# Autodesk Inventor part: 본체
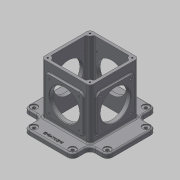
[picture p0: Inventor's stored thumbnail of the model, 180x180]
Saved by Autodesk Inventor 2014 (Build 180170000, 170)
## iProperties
Created: 2018-09
Part Number: 본체
Material: 알루미늄 6061
Document SubType Name: Modeling
Designer: mduedu
Density: 2.71 g/cm^3
Appearance: 기본값
Mass: 1126.64 g
Surface Area: 1144.86 cm^2
Volume: 415.735 cm^3
Author: mduedu
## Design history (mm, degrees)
sketch "스케치1"
  geometry: L1 (90, 52.5)-(-90, 52.5); L2 (-90, 52.5)-(-90, -52.5); L3 (-90, -52.5)-(90, -52.5); L4 (90, -52.5)-(90, 52.5); L5 (90, 52.5)-(-90, -52.5); L6 (-90, 52.5)-(90, -52.5); L7 (-52.5, -90)-(52.5, -90); L8 (52.5, -90)-(52.5, 90); L9 (52.5, 90)-(-52.5, 90); L10 (-52.5, 90)-(-52.5, -90); L11 (-52.5, -90)-(52.5, 90); L12 (52.5, -90)-(-52.5, 90); 1 further point
  constraints: 24 end point, 4 midpoint, 4 parallel, 2 horizontal, 2 perpendicular
  dimensions: "d0" = 180 distance of L3.end L2.end; "d1" = 105 distance of L2.end L1.end; "d105" = 105 distance of L9.end L8.end; "d106" = 180 distance of L8.end L7.end
extrude "돌출1" new body sketch "스케치1" distance "d2" = 10; taper "d3" = 0 deg
fillet "모깎기16" dims "d107" = 11
sketch "스케치2"
  geometry: L1 (-52.5, -52.5)-(52.5, -52.5); L2 (52.5, -52.5)-(52.5, 52.5); L3 (52.5, 52.5)-(-52.5, 52.5); L4 (-52.5, 52.5)-(-52.5, -52.5); L5 (-52.5, -52.5)-(52.5, 52.5); L6 (52.5, -52.5)-(-52.5, 52.5); 1 further point
  constraints: 12 end point, 2 midpoint, 2 parallel, 1 horizontal, 1 perpendicular
  dimensions: "d4" = 105 distance of L3.end L2.end; "d5" = 105 distance of L2.end L1.end
extrude "돌출2" join sketch "스케치2" distance "d6" = 110; taper "d7" = 0 deg
sketch "스케치14"
  geometry: L1 (-52.5, 52.5)-(52.5, 52.5) reference; L2 (52.5, 52.5)-(52.5, -52.5) reference; L3 (52.5, -52.5)-(-52.5, -52.5) reference; L4 (-52.5, -52.5)-(-52.5, 52.5) reference; L5 (46.5, 46.5)-(-46.5, 46.5); L6 (-46.5, 46.5)-(-46.5, -46.5); L7 (-46.5, -46.5)-(46.5, -46.5); L8 (46.5, -46.5)-(46.5, 46.5); 1 further point
  constraints: 8 end point, 3 other
  dimensions: "d85" = 6 distance between parallel lines of L5 L1
extrude "돌출10" cut sketch "스케치14" stored distance "d86" = 10; taper "d87" = 0 deg
fillet "모깎기1" dims "d12" = 7
sketch "스케치15"
  geometry: A1 r 7 centre (-45.5, 45.5) between (-45.5, 52.5) and (-52.5, 45.5) reference; A2 r 7 centre (45.5, 45.5) between (52.5, 45.5) and (45.5, 52.5) reference; A3 r 7 centre (45.5, -45.5) between (45.5, -52.5) and (52.5, -45.5) reference; A4 r 7 centre (-45.5, -45.5) between (-52.5, -45.5) and (-45.5, -52.5) reference; 5 further points
  constraints: 4 coincident, 4 vertical alignment, 8 other
extrude "돌출11" join sketch "스케치15" stored distance "d88" = 10; taper "d89" = 0 deg
fillet "모깎기15" dims "d90" = 3
sketch "스케치6"
  geometry: L1 (50, 20)-(130, 20); L2 (130, 20)-(130, 100); L3 (130, 100)-(50, 100); L4 (50, 100)-(50, 20); L5 (50, 20)-(130, 100); L6 (130, 20)-(50, 100); L7 (0, 0)-(180, 0) reference; 4 further points
  constraints: 12 end point, 4 midpoint, 2 parallel, 1 horizontal, 1 perpendicular, 1 vertical alignment
  dimensions: "d25" = 80 distance of L3.end L2.end; "d26" = 80 distance of L2.end L1.end; "d27" = 60 distance of point (90, 0) point (90, 60)
extrude "돌출6" join sketch "스케치6" distance "d28" = 3; taper "d29" = 0 deg
fillet "모깎기7" dims "d30" = 8
sketch "스케치7"
  geometry: C1 r 32.5 at (90, 60); 1 further point
  constraints: 1 centre point, 1 vertical alignment
  dimensions: "d32" = 65 diameter of C1; "d33" = 60 distance of C1.centre point (90, 0)
extrude "돌출7" cut sketch "스케치7" stored distance "d34" = 3; taper "d35" = 0 deg
fillet "모깎기9" dims "d36" = 3
sketch "스케치8"
  geometry: L1 (5.5, 10)-(85.5, 10); L2 (85.5, 10)-(85.5, 90); L3 (85.5, 90)-(5.5, 90); L4 (5.5, 90)-(5.5, 10); L5 (5.5, 10)-(85.5, 90); L6 (85.5, 10)-(5.5, 90); L7 (-7, -10)-(98, -10) reference; C1 r 32.5 at (45.5, 50); 4 further points
  constraints: 12 end point, 4 midpoint, 2 parallel, 1 centre point, 1 coincident, 1 horizontal, 1 perpendicular, 1 vertical alignment
  dimensions: "d37" = 80 distance of L3.end L2.end; "d38" = 80 distance of L2.end L1.end; "d39" = 60 distance from line of point (45.5, 50) L7; "d40" = 65 diameter of C1
extrude "돌출8" join sketch "스케치8" distance "d41" = 3; taper "d42" = 0 deg
fillet "모깎기10" dims "d43" = 8
extrude "돌출9" cut sketch "스케치8" stored distance "d44" = 3; taper "d45" = 0 deg
fillet "모깎기11" dims "d46" = 3
sketch "스케치9"
  geometry: L1 (50, 92)-(50, 28) reference; L2 (58, 20)-(122, 20) reference; L3 (130, 28)-(130, 92) reference; L4 (122, 100)-(58, 100) reference; C1 r 32.5 at (90, 60) reference; A1 r 8 centre (58, 92) between (58, 100) and (50, 92) reference; A2 r 8 centre (58, 28) between (50, 28) and (58, 20) reference; A3 r 8 centre (122, 28) between (122, 20) and (130, 28) reference; A4 r 8 centre (122, 92) between (130, 92) and (122, 100) reference; 5 further points
  constraints: 4 coincident
hole "구멍1" sketch "스케치9" at (58, 92), (122, 92), (122, 28), (58, 28) diameter "d47" = 3.242; stored, may be unused: countersink angle "d51" = 90 deg, drill point angle "d53" = 118 deg; dims "d48" = 6, "d49" = 4, "d50" = 2, "d52" = 9
sketch "스케치10"
  geometry: L1 (13.5, 10)-(77.5, 10) reference; L2 (85.5, 18)-(85.5, 82) reference; L3 (77.5, 90)-(13.5, 90) reference; L4 (5.5, 82)-(5.5, 18) reference; C1 r 32.5 at (45.5, 50) reference; A1 r 8 centre (13.5, 18) between (5.5, 18) and (13.5, 10) reference; A2 r 8 centre (77.5, 18) between (77.5, 10) and (85.5, 18) reference; A3 r 8 centre (77.5, 82) between (85.5, 82) and (77.5, 90) reference; A4 r 8 centre (13.5, 82) between (13.5, 90) and (5.5, 82) reference; 5 further points
  constraints: 4 coincident
hole "구멍2" sketch "스케치10" at (13.5, 82), (77.5, 82), (77.5, 18), (13.5, 18) diameter "d54" = 3.242; stored, may be unused: countersink angle "d58" = 90 deg, drill point angle "d60" = 118 deg; dims "d55" = 6, "d56" = 4, "d57" = 2, "d59" = 9
fillet "모깎기12" dims "d68" = 11
sketch "스케치16"
  geometry: A1 r 11 centre (-79, 41.5) between (-79, 52.5) and (-90, 41.5) reference; A2 r 11 centre (-79, -41.5) between (-90, -41.5) and (-79, -52.5) reference; A3 r 11 centre (79, 41.5) between (90, 41.5) and (79, 52.5) reference; A4 r 11 centre (79, -41.5) between (79, -52.5) and (90, -41.5) reference; A5 r 11 centre (-41.5, 79) between (-41.5, 90) and (-52.5, 79) reference; A6 r 11 centre (41.5, 79) between (52.5, 79) and (41.5, 90) reference; A7 r 11 centre (41.5, -79) between (41.5, -90) and (52.5, -79) reference; A8 r 11 centre (-41.5, -79) between (-52.5, -79) and (-41.5, -90) reference; 9 further points
  constraints: 8 coincident
hole "구멍5" sketch "스케치16" at (-79, 41.5), (79, 41.5), (79, -41.5), (-79, -41.5), (41.5, 79), (-41.5, 79), (-41.5, -79), (41.5, -79) diameter "d91" = 6.6; stored, may be unused: countersink angle "d95" = 90 deg, drill point angle "d97" = 118 deg; dims "d92" = 6, "d93" = 15, "d94" = 2, "d96" = 8
fillet "모깎기13" dims "d77" = 3
chamfer "모따기1" distance "d79" = 1; stored, may be unused: second distance "d80" = 2, angle "d81" = 45 deg
sketch "스케치17"
  geometry: A1 r 7 centre (-45.5, 45.5) between (-45.5, 52.5) and (-52.5, 45.5) reference; A2 r 7 centre (-45.5, -45.5) between (-52.5, -45.5) and (-45.5, -52.5) reference; A3 r 7 centre (45.5, -45.5) between (45.5, -52.5) and (52.5, -45.5) reference; A4 r 7 centre (45.5, 45.5) between (52.5, 45.5) and (45.5, 52.5) reference; 5 further points
  constraints: 4 coincident
hole "구멍6" sketch "스케치17" at (-45.5, 45.5), (45.5, 45.5), (45.5, -45.5), (-45.5, -45.5) diameter "d98" = 3.242; stored, may be unused: countersink angle "d102" = 90 deg, drill point angle "d104" = 118 deg; dims "d99" = 8, "d100" = 15, "d101" = 2, "d103" = 10
sketch "스케치13"
  geometry: L1 (90, -41.5)-(90, 41.5) reference; 2 further points
  constraints: 1 horizontal alignment, 1 other
  dimensions: "d82" = 11 distance from line of point (79, 0) L1
feature "엠보싱1" sketch "스케치13" dims "d0" = 180, "d1" = 105, "d83" = 0.5, "d84" = 0
node "솔리드1"
mirror "대칭1"
mirror "대칭4"
mirror "대칭2"
mirror "대칭5"
node "투영된 루프2"
node "투영된 루프3"
node "투영된 루프6"
